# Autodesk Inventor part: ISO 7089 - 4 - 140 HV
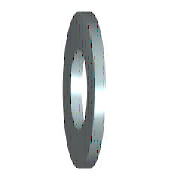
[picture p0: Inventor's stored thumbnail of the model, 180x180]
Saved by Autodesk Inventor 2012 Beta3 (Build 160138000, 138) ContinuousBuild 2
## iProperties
IsCustomPart: 0
Created: 2010-02
Part Number: ISO 7089 - 4 - 140 HV
Material: Stainless Steel
Description: Plain washers - Normal series - Product grade A
Document SubType Name: Modeling
Standard: ISO 7089
Designer: Thom Tremblay
Standard Revision: Second edition 2000-06-01
Standards Organization: ISO
Language: en-US
Size Designation: 4 - 140 HV
Categories: <MemberInstance><Categories><Category DisplayName="Fasteners" InternalName="e4da775c-781d-43d5-af7c-5136215cf5a6" Mnemonic="FSTN"><Category DisplayName="Washers
Density: 8.08 g/cm^3
Author: Thom Tremblay
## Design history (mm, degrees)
body "Solid1"
sketch "Sketch"
  geometry: C1 r 4.5 at (0, 0); C2 r 2.15 at (0, 0); 1 further point
  constraints: 2 centre point, 2 coincident
  dimensions: "d0" = 4.3 diameter of C2 (= SD1); "d1" = 9 diameter of C1 (= SD2)
extrude "Body" new body sketch "Sketch" distance "d2" = 0.8 (= SD); taper "d3" = 0 deg
workaxis "Work Axis1"
workplane "Work Plane1"
other parameters: "SD1" = 4.3 [user parameter; used in 1 equation term], "SD2" = 9 [user parameter; used in 1 equation term], "SD" = 0.8 [user parameter; used in 1 equation term], "d4" = 0, "d5" = 0, "d6" = 0, "d7" = 0, "NND" = 4 [user parameter]
